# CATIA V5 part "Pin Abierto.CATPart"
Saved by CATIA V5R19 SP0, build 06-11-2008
Part number: Pin Abierto
Publications: "Plane.1"
Material "Chroma": density 7190 kg/m3, Young's modulus 7e+10 Pa, Poisson ratio 0.3, thermal expansion 6.2e-06 1/K
Bounding box of the stored display mesh (mm): x -115.8 to 115.8, y -13.2 to 13.2, z -13.2 to 13.2
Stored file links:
  E:\Luis\Dropbox\3DIT\Parking\planos\cat 3 dit park8\Pin Abierto.CATPart
  E:\Luis\Dropbox\3DIT\Parking\planos\cat 3 dit park8\Eslabon de Cadena.........................................CATProduct
  E:\Luis\Dropbox\3DIT\Parking\planos\cat 3 dit park8\Parametros cadena.CATPart
  C:\Program Files (x86)\Dassault Systemes\B19\intel_a\startup\materials\Catalog.CATMaterial
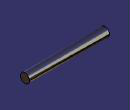
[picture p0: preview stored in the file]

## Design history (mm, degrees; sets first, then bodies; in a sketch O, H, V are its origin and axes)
Parameters
  d2 = 26.4
  i2 = 154.4
AxisSystem1: origin (0, 0, 0), X (1, 0, 0), Y (0, 1, 0), Z (0, 0, 1)
Set1
  Plane1: stored without definition
Body1 (main body), material "Chroma"
  Sketch1 on yz-plane, origin (0, 0, 0), H (0, 1, 0), V (0, 0, 1)
    circle A1 centre (0, 0) radius 13.2
    radius A1 = 13.2 {= d2 /2/1000}
  Pad1: profile Sketch1, direction (-1, 0, 0), length 115.8 {= i2*3/4/1000}, mirrored extent
Relations
  Pad1.SecondLimit.Length = `External Parameters\i2` /2/1000 (deactivated)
